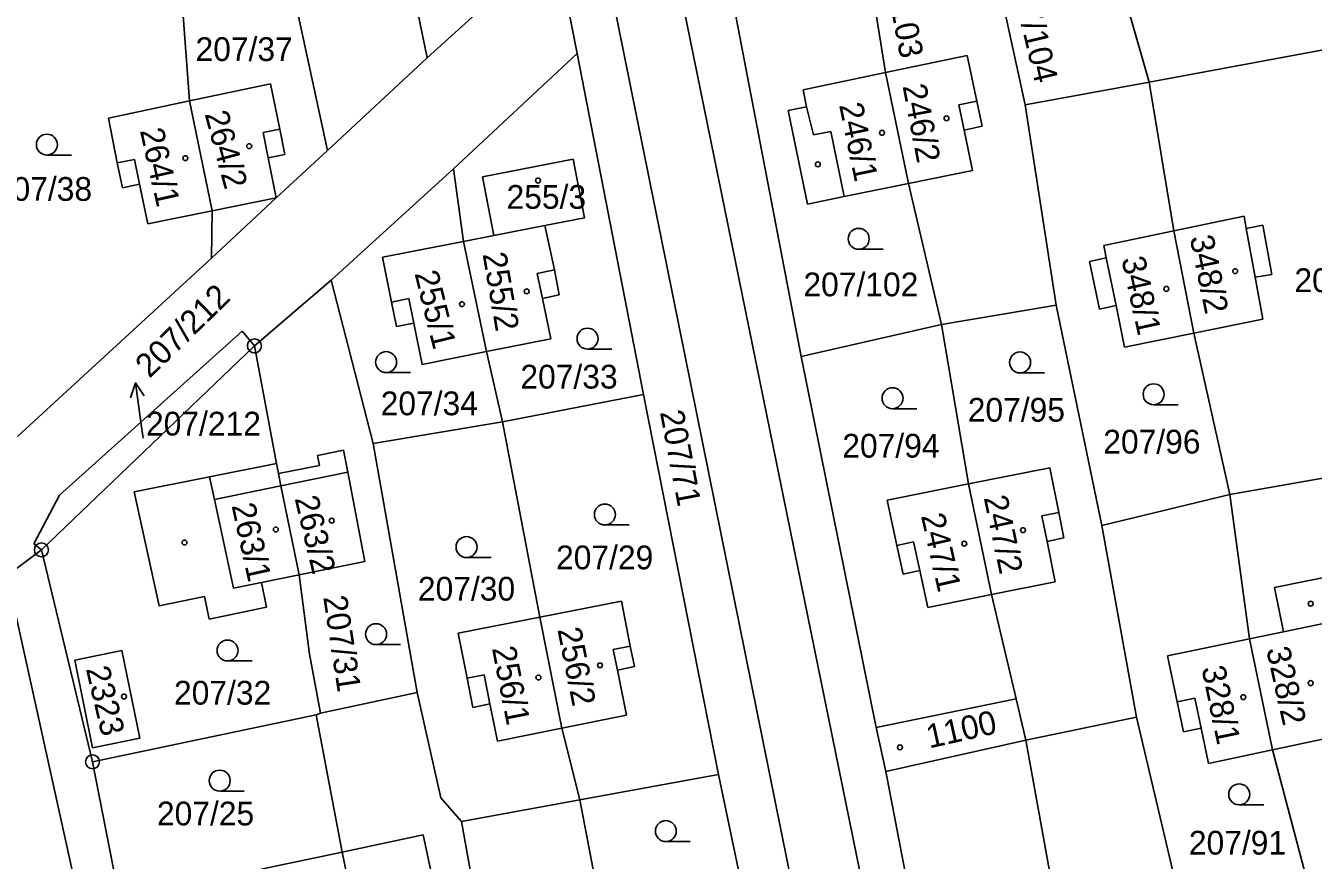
# Model space of a CAD drawing. Extents: x -735249 to -729401, y -1124843 to -1121828.
# Drawn here: x -733434 to -733341.9, y -1123667.8 to -1123608.1 of the extents above; entities that cross this region are included whole.
import ezdxf

# ---------------------------------------------------------------- set-up
doc = ezdxf.new("R2010")
doc.units = 0
for name, color, linetype in [('Vrstva 1', 7, 'Continuous'), ('Vrstva 16', 7, 'Continuous'), ('Vrstva 18', 7, 'Continuous'), ('Vrstva 19', 7, 'Continuous'), ('Vrstva 25', 7, 'Continuous'), ('Vrstva 4', 7, 'Continuous')]:
    doc.layers.add(name, color=color, linetype=linetype)

msp = doc.modelspace()

# ---------------------------------------------------------------- linework, layer by layer
at = {"layer": 'Vrstva 1'}
for points in [[(-733362, -1123729.19), (-733408.72, -1123500)], [(-733365.88, -1123598.36), (-733362.52, -1123613.78)], [(-733364.88, -1123740.38), (-733393.31, -1123599.68)], [(-733372.5, -1123611.48), (-733374.33, -1123600.04)], [(-733415.83, -1123601.14), (-733412.4, -1123617.06)], [(-733356.75, -1123601.3), (-733353.64, -1123612.16)], [(-733396.12, -1123602.13), (-733405.28, -1123610.42)], [(-733396.12, -1123602.13), (-733394.56, -1123610.12)], [(-733384.18, -1123602.31), (-733378.54, -1123631.79)], [(-733422.27, -1123613.5), (-733423.04, -1123603.21)], [(-733406.49, -1123604.48), (-733405.28, -1123610.42)], [(-733338.76, -1123609.39), (-733353.64, -1123612.16)], [(-733405.28, -1123610.42), (-733412.4, -1123617.06)], [(-733403.4, -1123618.37), (-733394.56, -1123610.12)], [(-733394.56, -1123610.12), (-733389.81, -1123634.5)], [(-733372.5, -1123611.48), (-733366.67, -1123610.25)], [(-733366.67, -1123610.25), (-733365.98, -1123613.51)], [(-733378.39, -1123612.71), (-733372.5, -1123611.48)], [(-733372.5, -1123611.48), (-733370.86, -1123619.41)], [(-733416.48, -1123612.27), (-733422.27, -1123613.5)], [(-733416.48, -1123612.27), (-733415.82, -1123615.52)], [(-733378.14, -1123613.93), (-733378.39, -1123612.71)], [(-733353.64, -1123612.16), (-733362.52, -1123613.78)], [(-733353.64, -1123612.16), (-733351.88, -1123622.8)], [(-733428.07, -1123614.73), (-733422.27, -1123613.5)], [(-733422.27, -1123613.5), (-733420.66, -1123621.36)], [(-733365.98, -1123613.51), (-733365.6, -1123615.32)], [(-733379.46, -1123614.2), (-733378.14, -1123613.93)], [(-733378.09, -1123620.89), (-733379.46, -1123614.2)], [(-733362.52, -1123613.78), (-733360.3, -1123628.12)], [(-733428.07, -1123614.73), (-733427.44, -1123617.93)], [(-733415.46, -1123617.33), (-733415.82, -1123615.52)], [(-733365.6, -1123615.32), (-733366.87, -1123615.59)], [(-733366.87, -1123615.59), (-733366.27, -1123618.47)], [(-733416.65, -1123617.57), (-733415.46, -1123617.33)], [(-733412.4, -1123617.06), (-733416.07, -1123620.43)], [(-733427.44, -1123617.93), (-733427.05, -1123619.71)], [(-733416.07, -1123620.43), (-733416.65, -1123617.57)], [(-733401.33, -1123618.94), (-733394.84, -1123617.67)], [(-733394.84, -1123617.67), (-733394.03, -1123621.87)], [(-733412.14, -1123626.33), (-733403.4, -1123618.37)], [(-733402.67, -1123623.55), (-733403.4, -1123618.37)], [(-733400.51, -1123623.13), (-733401.33, -1123618.94)], [(-733370.86, -1123619.41), (-733366.27, -1123618.47)], [(-733427.05, -1123619.71), (-733425.84, -1123619.46)], [(-733425.26, -1123622.29), (-733425.84, -1123619.46)], [(-733370.86, -1123619.41), (-733375.45, -1123620.35)], [(-733370.86, -1123619.41), (-733368.49, -1123629.49)], [(-733420.7, -1123624.75), (-733416.07, -1123620.43)], [(-733375.45, -1123620.35), (-733378.09, -1123620.89)], [(-733425.26, -1123622.29), (-733420.66, -1123621.36)], [(-733420.66, -1123621.36), (-733420.7, -1123624.75)], [(-733394.03, -1123621.87), (-733396.87, -1123622.42)], [(-733351.88, -1123622.8), (-733346.86, -1123621.75)], [(-733346.86, -1123621.75), (-733346.7, -1123622.62)], [(-733400.51, -1123623.13), (-733396.87, -1123622.42)], [(-733396.87, -1123622.42), (-733396.18, -1123625.59)], [(-733356.9, -1123623.84), (-733351.88, -1123622.8)], [(-733351.88, -1123622.8), (-733350.46, -1123630.12)], [(-733346.7, -1123622.62), (-733345.51, -1123622.4)], [(-733345.51, -1123622.4), (-733344.87, -1123625.91)], [(-733408.46, -1123624.68), (-733402.67, -1123623.55)], [(-733402.67, -1123623.55), (-733400.51, -1123623.13)], [(-733402.67, -1123623.55), (-733401.04, -1123631.44)], [(-733356.9, -1123623.84), (-733356.72, -1123624.73)], [(-733420.7, -1123624.75), (-733434.56, -1123637.51)], [(-733408.46, -1123624.68), (-733407.82, -1123627.89)], [(-733357.92, -1123624.98), (-733356.72, -1123624.73)], [(-733396.18, -1123625.59), (-733395.84, -1123627.38)], [(-733357.21, -1123628.4), (-733357.92, -1123624.98)], [(-733417.63, -1123631.03), (-733412.14, -1123626.33)], [(-733412.14, -1123626.33), (-733409.14, -1123638.01)], [(-733344.87, -1123625.91), (-733346.06, -1123626.12)], [(-733345.52, -1123629.11), (-733346.06, -1123626.12)], [(-733395.84, -1123627.38), (-733397.04, -1123627.63)], [(-733407.82, -1123627.89), (-733407.46, -1123629.65)], [(-733396.44, -1123630.52), (-733397.04, -1123627.63)], [(-733368.49, -1123629.49), (-733360.3, -1123628.12)], [(-733360.3, -1123628.12), (-733357.04, -1123643.87)], [(-733356.01, -1123628.15), (-733357.21, -1123628.4)], [(-733355.4, -1123631.13), (-733356.01, -1123628.15)], [(-733345.52, -1123629.11), (-733350.46, -1123630.12)], [(-733431.57, -1123641.71), (-733418.5, -1123629.98)], [(-733418.5, -1123629.98), (-733417.63, -1123631.03)], [(-733407.46, -1123629.65), (-733406.23, -1123629.4)], [(-733405.64, -1123632.36), (-733406.23, -1123629.4)], [(-733378.54, -1123631.79), (-733368.49, -1123629.49)], [(-733368.49, -1123629.49), (-733366.56, -1123640.9)], [(-733350.46, -1123630.12), (-733355.4, -1123631.13)], [(-733350.46, -1123630.12), (-733347.88, -1123641.66)], [(-733432.86, -1123645.62), (-733417.63, -1123631.03)], [(-733417.63, -1123631.03), (-733416.05, -1123639.45)], [(-733396.44, -1123630.52), (-733401.04, -1123631.44)], [(-733401.04, -1123631.44), (-733405.64, -1123632.36)], [(-733401.04, -1123631.44), (-733399.9, -1123636.46)], [(-733373.16, -1123658.32), (-733378.54, -1123631.79)], [(-733399.9, -1123636.46), (-733389.81, -1123634.5)], [(-733389.81, -1123634.5), (-733384.45, -1123661.68)], [(-733409.14, -1123638.01), (-733399.9, -1123636.46)], [(-733399.9, -1123636.46), (-733397.23, -1123650.43)], [(-733411.27, -1123638.49), (-733413.12, -1123638.86)], [(-733411.27, -1123638.49), (-733410.96, -1123640.07)], [(-733409.14, -1123638.01), (-733405.98, -1123655.82)], [(-733416.05, -1123639.45), (-733420.83, -1123640.4)], [(-733416.05, -1123639.45), (-733415.91, -1123640.16)], [(-733413.12, -1123638.86), (-733412.97, -1123639.58)], [(-733332.54, -1123638.96), (-733347.88, -1123641.66)], [(-733420.83, -1123640.4), (-733426.23, -1123641.48)], [(-733412.97, -1123639.58), (-733415.91, -1123640.16)], [(-733415.91, -1123640.16), (-733415.73, -1123641.04)], [(-733409.73, -1123646.45), (-733410.96, -1123640.07)], [(-733366.56, -1123640.9), (-733360.76, -1123639.74)], [(-733360.11, -1123642.95), (-733360.76, -1123639.74)], [(-733414.44, -1123647.41), (-733415.73, -1123641.04)], [(-733372.38, -1123642.07), (-733366.56, -1123640.9)], [(-733366.56, -1123640.9), (-733364.92, -1123648.82)], [(-733433.4, -1123645.2), (-733431.57, -1123641.71)], [(-733426.23, -1123641.48), (-733424.45, -1123649.62)], [(-733372.38, -1123642.07), (-733371.69, -1123645.31)], [(-733347.88, -1123641.66), (-733357.04, -1123643.87)], [(-733346.48, -1123651.99), (-733347.88, -1123641.66)], [(-733359.75, -1123644.77), (-733360.11, -1123642.95)], [(-733357.04, -1123643.87), (-733354.55, -1123657.59)], [(-733360.95, -1123645.01), (-733359.75, -1123644.77)], [(-733360.37, -1123647.9), (-733360.95, -1123645.01)], [(-733435.32, -1123647.45), (-733432.86, -1123645.62)], [(-733432.86, -1123645.62), (-733433.4, -1123645.2)], [(-733429.21, -1123660.78), (-733432.86, -1123645.62)], [(-733371.69, -1123645.31), (-733371.24, -1123647.35)], [(-733414.44, -1123647.41), (-733409.73, -1123646.45)], [(-733428.44, -1123678.6), (-733435.32, -1123647.45)], [(-733417.12, -1123647.95), (-733414.44, -1123647.41)], [(-733413.7, -1123653.09), (-733414.44, -1123647.41)], [(-733371.24, -1123647.35), (-733370.05, -1123647.1)], [(-733370.05, -1123647.1), (-733369.48, -1123649.74)], [(-733344.68, -1123648.31), (-733340.09, -1123647.38)], [(-733416.76, -1123649.73), (-733417.12, -1123647.95)], [(-733364.92, -1123648.82), (-733360.37, -1123647.9)], [(-733344.04, -1123651.49), (-733344.68, -1123648.31)], [(-733424.45, -1123649.62), (-733421.2, -1123648.96)], [(-733421.2, -1123648.96), (-733420.87, -1123650.57)], [(-733397.23, -1123650.43), (-733391.39, -1123649.28)], [(-733391.39, -1123649.28), (-733390.77, -1123652.51)], [(-733364.92, -1123648.82), (-733369.48, -1123649.74)], [(-733364.92, -1123648.82), (-733363.16, -1123656.28)], [(-733420.87, -1123650.57), (-733416.76, -1123649.73)], [(-733403.07, -1123651.58), (-733397.23, -1123650.43)], [(-733397.23, -1123650.43), (-733395.64, -1123658.37)], [(-733402.42, -1123654.8), (-733403.07, -1123651.58)], [(-733352.34, -1123653.2), (-733346.48, -1123651.99)], [(-733346.48, -1123651.99), (-733344.04, -1123651.49)], [(-733346.48, -1123651.99), (-733344.82, -1123659.92)], [(-733430.47, -1123653.5), (-733427.1, -1123652.81)], [(-733427.1, -1123652.81), (-733425.82, -1123659.1)], [(-733412.91, -1123657.3), (-733413.7, -1123653.09)], [(-733390.77, -1123652.51), (-733390.44, -1123653.97)], [(-733352.34, -1123653.2), (-733351.64, -1123656.5)], [(-733429.2, -1123659.78), (-733430.47, -1123653.5)], [(-733390.44, -1123653.97), (-733391.67, -1123654.23)], [(-733391.67, -1123654.23), (-733391.02, -1123657.44)], [(-733402, -1123656.89), (-733402.42, -1123654.8)], [(-733405.98, -1123655.82), (-733412.91, -1123657.3)], [(-733405.98, -1123655.82), (-733404.29, -1123663.36)], [(-733400.79, -1123656.64), (-733402, -1123656.89)], [(-733400.25, -1123659.31), (-733400.79, -1123656.64)], [(-733363.16, -1123656.28), (-733373.16, -1123658.32)], [(-733362.47, -1123659.24), (-733363.16, -1123656.28)], [(-733351.64, -1123656.5), (-733351.19, -1123658.63)], [(-733413.21, -1123657.41), (-733429.21, -1123660.78)], [(-733412.91, -1123657.3), (-733413.21, -1123657.41)], [(-733411.36, -1123667.24), (-733413.21, -1123657.41)], [(-733391.02, -1123657.44), (-733395.64, -1123658.37)], [(-733354.55, -1123657.59), (-733362.47, -1123659.24)], [(-733354.55, -1123657.59), (-733350.96, -1123672.86)], [(-733395.64, -1123658.37), (-733400.25, -1123659.31)], [(-733395.64, -1123658.37), (-733394.36, -1123663.5)], [(-733373.16, -1123658.32), (-733372.47, -1123661.47)], [(-733351.19, -1123658.63), (-733349.94, -1123658.37)], [(-733349.94, -1123658.37), (-733349.4, -1123660.9)], [(-733425.82, -1123659.1), (-733429.2, -1123659.78)], [(-733362.47, -1123659.24), (-733372.47, -1123661.47)], [(-733360.49, -1123670.18), (-733362.47, -1123659.24)], [(-733340.24, -1123658.95), (-733344.82, -1123659.92)], [(-733344.82, -1123659.92), (-733349.4, -1123660.9)], [(-733344.82, -1123659.92), (-733341.84, -1123671.2)], [(-733429.21, -1123660.78), (-733423.8, -1123688.37)], [(-733372.47, -1123661.47), (-733366.73, -1123691.4)], [(-733384.45, -1123661.68), (-733394.36, -1123663.5)], [(-733384.45, -1123661.68), (-733379.38, -1123685.88)], [(-733404.29, -1123663.36), (-733402.81, -1123665.06)], [(-733394.36, -1123663.5), (-733402.81, -1123665.06)], [(-733394.36, -1123663.5), (-733391.7, -1123677.47)], [(-733402.81, -1123665.06), (-733399.57, -1123683.16)], [(-733411.36, -1123667.24), (-733405.57, -1123666.01)], [(-733405.57, -1123666.01), (-733404.88, -1123669.24)], [(-733417.14, -1123668.46), (-733411.36, -1123667.24)], [(-733409.7, -1123675.21), (-733411.36, -1123667.24)]]:
    msp.add_lwpolyline(points, dxfattribs=at)
at = {"layer": 'Vrstva 16'}
msp.add_lwpolyline([(-733425.58, -1123637.64), (-733425.72, -1123636.65)], dxfattribs=at)
at = {"layer": 'Vrstva 25'}
for points in [[(-733432.47, -1123617.38), (-733430.72, -1123617.38)], [(-733374.42, -1123624.12), (-733372.67, -1123624.12)], [(-733393.81, -1123631.26), (-733392.06, -1123631.26)], [(-733408.21, -1123632.94), (-733406.46, -1123632.94)], [(-733362.88, -1123632.96), (-733361.13, -1123632.96)], [(-733426.493, -1123634.74), (-733426.137, -1123633.68), (-733425.504, -1123634.6)], [(-733425.72, -1123636.65), (-733426.137, -1123633.68)], [(-733372, -1123635.52), (-733370.25, -1123635.52)], [(-733353.33, -1123635.24), (-733351.58, -1123635.24)], [(-733392.57, -1123643.84), (-733390.82, -1123643.84)], [(-733402.46, -1123646.17), (-733400.71, -1123646.17)], [(-733408.93, -1123652.4), (-733407.18, -1123652.4)], [(-733419.55, -1123653.57), (-733417.8, -1123653.57)], [(-733420.11, -1123662.88), (-733418.36, -1123662.88)], [(-733347.21, -1123663.86), (-733345.46, -1123663.86)], [(-733388.21, -1123666.49), (-733386.46, -1123666.49)]]:
    msp.add_lwpolyline(points, dxfattribs=at)
for centre, radius in [((-733368.14, -1123614.75), 0.175), ((-733432.47, -1123616.63), 0.75), ((-733372.75, -1123615.78), 0.175), ((-733418, -1123616.74), 0.175), ((-733422.57, -1123617.6), 0.175), ((-733377.34, -1123618.04), 0.175), ((-733397.35, -1123619.2), 0.175), ((-733374.42, -1123623.37), 0.75), ((-733347.5, -1123625.68), 0.175), ((-733398.16, -1123627.13), 0.175), ((-733352.42, -1123626.95), 0.175), ((-733402.79, -1123628.04), 0.175), ((-733393.81, -1123630.51), 0.75), ((-733417.63, -1123631.03), 0.5), ((-733417.63, -1123631.03), 0.032), ((-733408.21, -1123632.19), 0.75), ((-733362.88, -1123632.21), 0.75), ((-733353.33, -1123634.49), 0.75), ((-733372, -1123634.77), 0.75), ((-733392.57, -1123643.09), 0.75), ((-733416.1, -1123644.16), 0.175), ((-733412.1, -1123643.53), 0.175), ((-733362.67, -1123644.21), 0.175), ((-733422.63, -1123645.09), 0.175), ((-733402.46, -1123645.42), 0.75), ((-733366.87, -1123645.18), 0.175), ((-733432.86, -1123645.62), 0.5), ((-733432.86, -1123645.62), 0.032), ((-733342.1, -1123649.47), 0.175), ((-733408.93, -1123651.65), 0.75), ((-733419.55, -1123652.82), 0.75), ((-733392.92, -1123653.88), 0.175), ((-733397.32, -1123654.75), 0.175), ((-733342.1, -1123655.15), 0.175), ((-733426.95, -1123656.11), 0.175), ((-733346.91, -1123656.16), 0.175), ((-733371.47, -1123659.75), 0.175), ((-733429.21, -1123660.78), 0.5), ((-733429.21, -1123660.78), 0.032), ((-733420.11, -1123662.13), 0.75), ((-733347.21, -1123663.11), 0.75), ((-733388.21, -1123665.74), 0.75)]:
    msp.add_circle(centre, radius, dxfattribs=at)
at = {"layer": 'Vrstva 4'}
for points in [[(-733367.25, -1123613.78), (-733365.98, -1123613.51)], [(-733378.14, -1123613.93), (-733377.66, -1123615.93)], [(-733366.87, -1123615.59), (-733367.25, -1123613.78)], [(-733415.82, -1123615.52), (-733417.01, -1123615.76)], [(-733417.01, -1123615.76), (-733416.65, -1123617.57)], [(-733377.66, -1123615.93), (-733376.4, -1123615.68)], [(-733376.4, -1123615.68), (-733375.45, -1123620.35)], [(-733427.44, -1123617.93), (-733426.2, -1123617.7)], [(-733426.2, -1123617.7), (-733425.84, -1123619.46)], [(-733420.66, -1123621.36), (-733416.07, -1123620.43)], [(-733346.7, -1123622.62), (-733346.06, -1123626.12)], [(-733356.72, -1123624.73), (-733356.01, -1123628.15)], [(-733396.18, -1123625.59), (-733397.41, -1123625.86)], [(-733397.41, -1123625.86), (-733397.04, -1123627.63)], [(-733407.82, -1123627.89), (-733406.58, -1123627.64)], [(-733406.58, -1123627.64), (-733406.23, -1123629.4)], [(-733420.83, -1123640.4), (-733420.49, -1123642.01)], [(-733415.73, -1123641.04), (-733410.96, -1123640.07)], [(-733420.49, -1123642.01), (-733415.73, -1123641.04)], [(-733419.13, -1123648.36), (-733420.49, -1123642.01)], [(-733360.11, -1123642.95), (-733361.32, -1123643.19)], [(-733361.32, -1123643.19), (-733360.95, -1123645.01)], [(-733371.69, -1123645.31), (-733370.49, -1123645.04)], [(-733370.49, -1123645.04), (-733370.05, -1123647.1)], [(-733419.13, -1123648.36), (-733417.12, -1123647.95)], [(-733340.62, -1123650.78), (-733344.04, -1123651.49)], [(-733390.77, -1123652.51), (-733391.97, -1123652.75)], [(-733391.97, -1123652.75), (-733391.67, -1123654.23)], [(-733402.42, -1123654.8), (-733401.21, -1123654.55)], [(-733401.21, -1123654.55), (-733400.79, -1123656.64)], [(-733351.64, -1123656.5), (-733350.39, -1123656.23)], [(-733350.39, -1123656.23), (-733349.94, -1123658.37)]]:
    msp.add_lwpolyline(points, dxfattribs=at)

# ---------------------------------------------------------------- texts
at = {"layer": 'Vrstva 16'}
msp.add_text('207/212', height=1.7, rotation=44.10035, dxfattribs=at).set_placement((-733425.136, -1123633.398))
at = {"layer": 'Vrstva 18'}
for s, rotation, p in [('207/103', 280.70223, (-733372.957, -1123602.469)), ('207/104', 283.30225, (-733363.69, -1123604.328)), ('207/71', 280.80223, (-733388.637, -1123635.768)), ('207/31', 278.70222, (-733412.713, -1123648.997))]:
    msp.add_text(s, height=1.7, rotation=rotation, dxfattribs=at).set_placement(p)
for s, p in [('207/37', (-733421.84, -1123610.65)), ('207/38', (-733436.19, -1123620.65)), ('207/102', (-733378.37, -1123627.48)), ('207/97', (-733343.26, -1123627.18)), ('207/33', (-733398.61, -1123634.08)), ('207/34', (-733408.6, -1123635.99)), ('207/95', (-733366.62, -1123636.45)), ('207/212', (-733425.38, -1123637.44)), ('207/94', (-733375.59, -1123639.02)), ('207/96', (-733356.93, -1123638.73)), ('207/29', (-733396.06, -1123647.01)), ('207/30', (-733405.94, -1123649.25)), ('207/32', (-733423.38, -1123656.69)), ('207/25', (-733424.6, -1123665.33)), ('207/91', (-733350.81, -1123667.42))]:
    msp.add_text(s, height=1.7, dxfattribs=at).set_placement(p)
at = {"layer": 'Vrstva 19'}
for s, rotation, p in [('246/2', 280.80223, (-733371.287, -1123612.438)), ('246/1', 281.60224, (-733375.824, -1123613.795)), ('264/2', 285.00227, (-733421.196, -1123614.431)), ('264/1', 282.60225, (-733425.822, -1123615.621)), ('348/2', 281.50224, (-733350.755, -1123623.266)), ('255/2', 279.80223, (-733401.319, -1123624.463)), ('348/1', 282.30224, (-733355.642, -1123624.802)), ('255/1', 284.00226, (-733406.188, -1123625.845)), ('263/1', 282.40225, (-733419.272, -1123642.442)), ('263/2', 283.40225, (-733414.76, -1123641.938)), ('247/2', 281.90224, (-733365.484, -1123641.884)), ('247/1', 282.70225, (-733369.971, -1123643.181)), ('256/2', 281.20224, (-733395.965, -1123651.317)), ('256/1', 281.00224, (-733400.646, -1123652.658)), ('328/2', 282.60225, (-733345.292, -1123652.731)), ('2323', 283.30225, (-733429.69, -1123654.128)), ('328/1', 281.70224, (-733349.914, -1123654.075)), ('1100', 12.7001, (-733369.369, -1123659.831))]:
    msp.add_text(s, height=1.7, rotation=rotation, dxfattribs=at).set_placement(p)
msp.add_text('255/3', height=1.7, dxfattribs=at).set_placement((-733399.6, -1123621.22))

doc.saveas('drawing.dxf')
